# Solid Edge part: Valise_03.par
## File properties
Author: Bernard DUMAS
Template: Normal.par
Last saved by: FR026244
Revision: 11
Application: Solid Edge
Material: Bois, Frêne
Style de face: Jaune kaki
Style de remplissage: Liège
Style virtuel: Frêne verni
Coef. of Thermal Exp: 0.0
Thermal Conductivity: 0.0
Specific Heat: 0.0
Modulus of Elasticity: 0.0
Poission's Ratio: 0.0
Yield Stress: 0.0
Ultimate Stress: 0.0
Elongation: 0.0
Densité: 460.000 kg/m^3
Précision: 0.9900
Document Number: 03
Revision: a
Project Name: Slamson
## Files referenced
..\Valise_Salmson.asm
bD:\Documents and Settings\FR026244\Mes Documents\Bernard\Slamson\Valise-Salmson\Valise_Salmson.asm
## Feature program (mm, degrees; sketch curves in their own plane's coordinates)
sketch for "unnamed Protrusion 1" plane through (0, 0, 0) normal (0, -1, 0) x-axis (1, 0, 0)
extrude "unnamed Protrusion 1" add to key point symmetric
extrude "unnamed Cutout 1" cut finite 6
extrude "Enlèvement_matière_2" cut finite 6
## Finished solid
Body 1: solid body, 10 faces, 24 edges, 16 vertices.
  Faces by surface: plane 10
  Edges by curve: line 24
Bounding box of the edges (mm): 58.208 x 850.000 x 103.000, from (446.7918, -425, 3) to (505, 425, 106).
Planar faces by outward normal: +y 2, +z 1, -y 2, -z 1, oblique 4
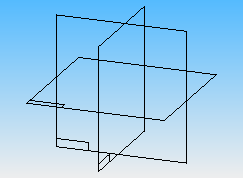
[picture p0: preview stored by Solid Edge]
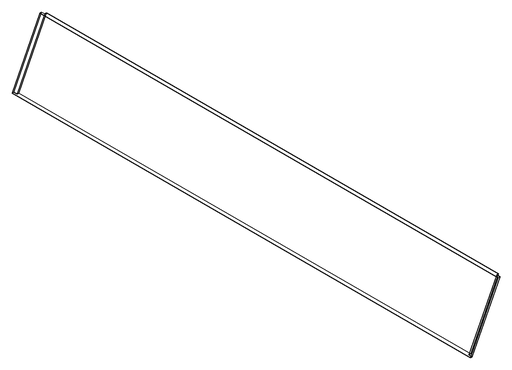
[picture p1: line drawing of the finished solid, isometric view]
